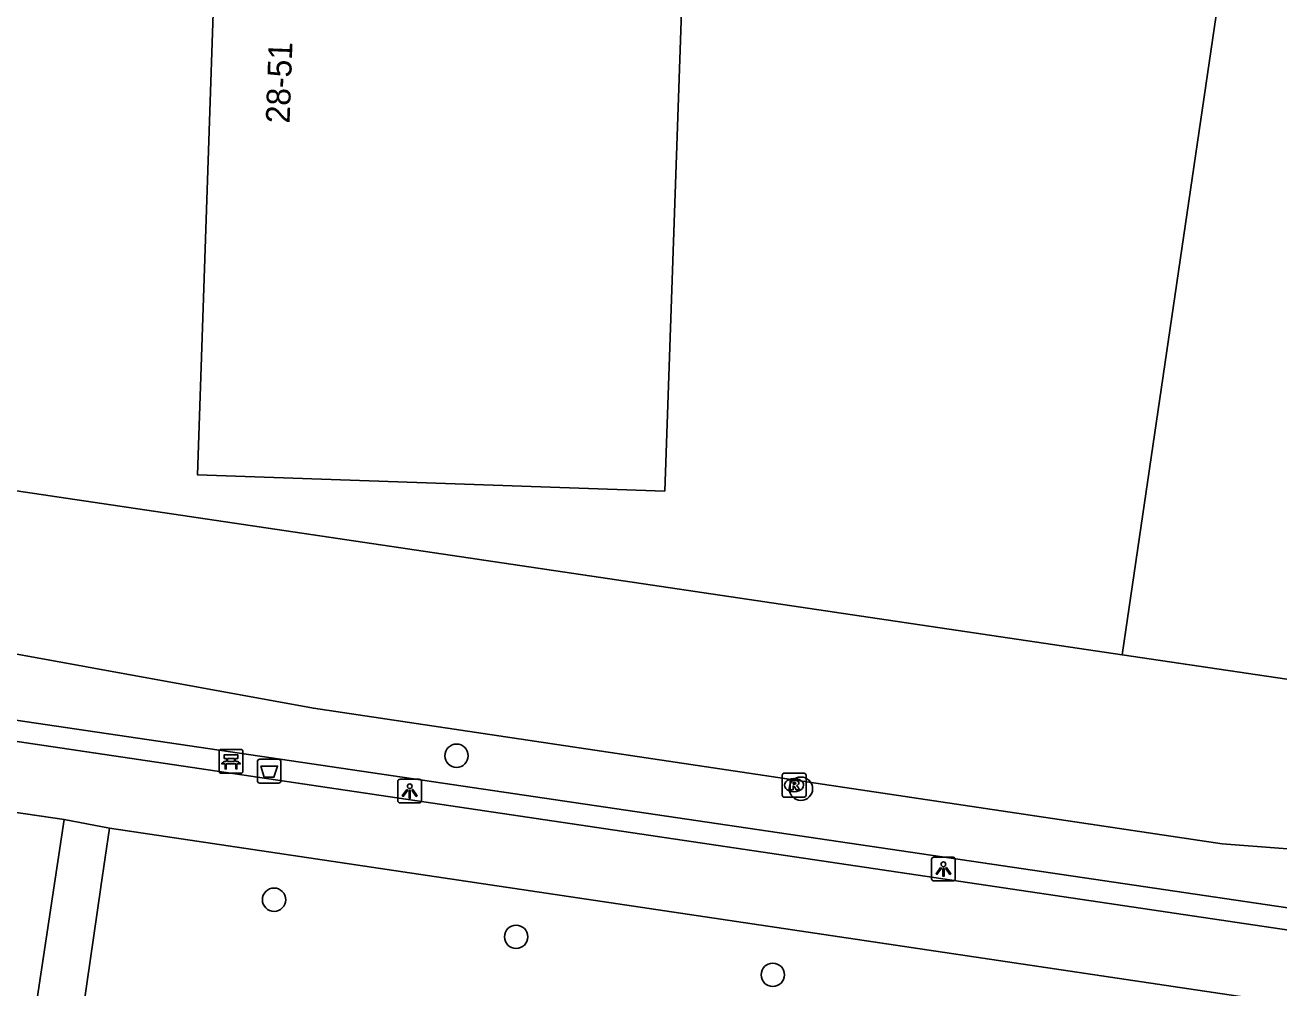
# Model space of a CAD drawing. Extents: x 164150 to 165261, y 382513 to 383432.
# Drawn here: x 164287.5 to 164340.1, y 383053.9 to 383094.3 of the extents above; entities that cross this region are included whole.
import ezdxf

# ---------------------------------------------------------------- set-up
doc = ezdxf.new("R2010")
doc.units = 0
for name, color, linetype in [('IMGEO_Afvalbak', 7, 'Continuous'), ('IMGEO_Bank', 7, 'Continuous'), ('IMGEO_Boom', 7, 'Continuous'), ('IMGEO_Fietspad_gesloten', 7, 'Continuous'), ('IMGEO_Fietspad_open', 7, 'Continuous'), ('IMGEO_Groenvoorziening', 7, 'Continuous'), ('IMGEO_Lichtpunt', 7, 'Continuous'), ('IMGEO_Muur', 7, 'Continuous'), ('IMGEO_Pand', 7, 'Continuous'), ('IMGEO_Pand_nummerreeks', 7, 'Continuous'), ('IMGEO_Rioolput', 7, 'Continuous'), ('IMGEO_Voetpad_open', 7, 'Continuous')]:
    doc.layers.add(name, color=color, linetype=linetype)

msp = doc.modelspace()

# ---------------------------------------------------------------- linework, layer by layer
at = {"layer": 'IMGEO_Afvalbak'}
for p, q in [((164297.213, 383062.583), (164297.213, 383063.383)), ((164297.213, 383063.383), (164297.213, 383062.583)), ((164297.313, 383063.483), (164298.103, 383063.483)), ((164298.103, 383063.483), (164297.313, 383063.483)), ((164298.203, 383063.383), (164298.203, 383062.583)), ((164298.203, 383062.583), (164298.203, 383063.383)), ((164298.103, 383062.483), (164297.313, 383062.483)), ((164297.313, 383062.483), (164298.103, 383062.483))]:
    msp.add_line(p, q, dxfattribs=at)
msp.add_lwpolyline([(164297.356, 383063.197), (164298.06, 383063.197), (164297.911, 383062.727), (164297.505, 383062.727), (164297.356, 383063.197)], dxfattribs=at)
for centre, start, end in [((164297.313, 383063.383), 90, 180), ((164297.313, 383063.383), 90, 180), ((164298.103, 383063.383), 0, 90), ((164298.103, 383063.383), 360, 90), ((164297.313, 383062.583), 180, 270), ((164297.313, 383062.583), 180, 270), ((164298.103, 383062.583), 270, 0), ((164298.103, 383062.583), 270, 0)]:
    msp.add_arc(centre, 0.1, start, end, dxfattribs=at)
at = {"layer": 'IMGEO_Bank'}
for p, q in [((164295.608, 383062.969), (164295.608, 383063.81)), ((164295.608, 383063.81), (164295.608, 383062.969)), ((164295.683, 383063.894), (164296.524, 383063.894)), ((164296.524, 383063.894), (164295.683, 383063.894)), ((164296.608, 383063.819), (164296.608, 383062.978)), ((164296.608, 383062.978), (164296.608, 383063.819)), ((164296.305, 383063.292), (164295.912, 383063.292)), ((164295.917, 383063.4), (164295.917, 383063.506)), ((164295.961, 383063.506), (164295.961, 383063.4)), ((164296.249, 383063.512), (164295.967, 383063.512)), ((164295.967, 383063.394), (164296.249, 383063.394)), ((164296.255, 383063.4), (164296.255, 383063.506)), ((164296.299, 383063.506), (164296.299, 383063.4)), ((164296.533, 383062.894), (164295.692, 383062.894)), ((164295.692, 383062.894), (164296.533, 383062.894))]:
    msp.add_line(p, q, dxfattribs=at)
for points in [[(164295.911, 383063.512), (164295.825, 383063.512), (164295.825, 383063.673), (164296.388, 383063.673), (164296.388, 383063.512), (164296.305, 383063.512)], [(164295.855, 383063.292), (164295.713, 383063.292), (164295.825, 383063.394), (164295.911, 383063.394)], [(164295.905, 383063.285), (164295.905, 383063.078), (164295.862, 383063.078), (164295.862, 383063.285)], [(164296.305, 383063.394), (164296.388, 383063.394), (164296.5, 383063.292), (164296.361, 383063.292)], [(164296.355, 383063.285), (164296.355, 383063.078), (164296.311, 383063.078), (164296.311, 383063.285)]]:
    msp.add_lwpolyline(points, dxfattribs=at)
for centre, radius, start, end in [((164295.686, 383063.816), 0.0779, 92.4484, 184.2845), ((164295.686, 383063.816), 0.0779, 92.4484, 184.2845), ((164296.53, 383063.816), 0.0779, 2.4484, 94.2845), ((164296.53, 383063.816), 0.0779, 2.4484, 94.2845), ((164295.855, 383063.285), 0.00671, 2.8957, 87.1043), ((164295.912, 383063.285), 0.00671, 92.8957, 177.1043), ((164295.91, 383063.505), 0.00671, 2.8957, 87.1043), ((164295.91, 383063.401), 0.00671, 272.8957, 357.1043), ((164295.967, 383063.505), 0.00671, 92.8957, 177.1043), ((164295.967, 383063.401), 0.00671, 182.8957, 267.1043), ((164296.249, 383063.505), 0.00671, 2.8957, 87.1043), ((164296.249, 383063.401), 0.00671, 272.8957, 357.1043), ((164296.306, 383063.505), 0.00671, 92.8957, 177.1043), ((164296.306, 383063.401), 0.00671, 182.8957, 267.1043), ((164296.304, 383063.285), 0.00671, 2.8957, 87.1043), ((164296.361, 383063.285), 0.00671, 92.8957, 177.1043), ((164295.686, 383062.972), 0.0779, 182.4484, 274.2845), ((164295.686, 383062.972), 0.0779, 182.4484, 274.2845), ((164296.53, 383062.972), 0.0779, 272.4484, 4.2845), ((164296.53, 383062.972), 0.0779, 272.4484, 4.2845)]:
    msp.add_arc(centre, radius, start, end, dxfattribs=at)
at = {"layer": 'IMGEO_Boom'}
for centre in [(164305.574, 383063.63), (164320.031, 383062.245), (164297.914, 383057.588), (164308.075, 383056.03), (164318.847, 383054.435)]:
    msp.add_circle(centre, 0.489, dxfattribs=at)
at = {"layer": 'IMGEO_Fietspad_gesloten'}
for points in [[(164371.722, 383051.672), (164265.706, 383067.397), (164250.971, 383069.441)], [(164289.109, 383060.95), (164241.04, 383067.994), (164239.423, 383068.201), (164236.742, 383068.586)], [(164289.109, 383060.95), (164291.001, 383060.584)], [(164291.001, 383060.584), (164349.656, 383051.856)]]:
    msp.add_lwpolyline(points, dxfattribs=at)
at = {"layer": 'IMGEO_Fietspad_open'}
for points in [[(164287.476, 383050.195), (164289.109, 383060.95)], [(164289.455, 383049.901), (164290.642, 383058.11), (164290.645, 383058.127), (164291.001, 383060.584)]]:
    msp.add_lwpolyline(points, dxfattribs=at)
at = {"layer": 'IMGEO_Groenvoorziening'}
for points in [[(164257.237, 383074.022), (164271.132, 383070.796), (164299.567, 383065.623), (164337.712, 383059.936), (164353.074, 383058.756)], [(164371.573, 383052.659), (164251.222, 383070.415)]]:
    msp.add_lwpolyline(points, dxfattribs=at)
at = {"layer": 'IMGEO_Lichtpunt'}
for p, q in [((164303.11, 383062.55), (164303.11, 383061.743)), ((164303.11, 383062.55), (164303.11, 383061.743)), ((164304.012, 383062.645), (164303.204, 383062.645)), ((164304.012, 383062.645), (164303.204, 383062.645)), ((164304.106, 383061.743), (164304.106, 383062.55)), ((164304.106, 383061.743), (164304.106, 383062.55)), ((164303.204, 383061.649), (164304.012, 383061.649)), ((164303.204, 383061.649), (164304.012, 383061.649)), ((164326.414, 383059.37), (164325.606, 383059.37)), ((164326.414, 383059.37), (164325.606, 383059.37)), ((164325.512, 383059.275), (164325.512, 383058.468)), ((164325.512, 383059.275), (164325.512, 383058.468)), ((164326.508, 383058.468), (164326.508, 383059.275)), ((164326.508, 383058.468), (164326.508, 383059.275)), ((164325.606, 383058.374), (164326.414, 383058.374)), ((164325.606, 383058.374), (164326.414, 383058.374))]:
    msp.add_line(p, q, dxfattribs=at)
for points in [[(164303.484, 383062.214), (164303.523, 383062.186), (164303.335, 383061.924), (164303.297, 383061.951), (164303.484, 383062.214)], [(164303.586, 383062.166), (164303.633, 383062.166), (164303.633, 383061.844), (164303.586, 383061.844), (164303.586, 383062.166)], [(164303.696, 383062.186), (164303.734, 383062.213), (164303.921, 383061.951), (164303.882, 383061.923), (164303.696, 383062.186)], [(164325.886, 383058.939), (164325.925, 383058.911), (164325.737, 383058.649), (164325.699, 383058.676), (164325.886, 383058.939)], [(164325.988, 383058.891), (164326.035, 383058.891), (164326.035, 383058.569), (164325.988, 383058.569), (164325.988, 383058.891)], [(164326.098, 383058.911), (164326.136, 383058.938), (164326.323, 383058.676), (164326.284, 383058.648), (164326.098, 383058.911)]]:
    msp.add_lwpolyline(points, dxfattribs=at)
for centre in [(164303.609, 383062.348), (164326.011, 383059.073)]:
    msp.add_circle(centre, 0.0994, dxfattribs=at)
for centre, start, end in [((164303.204, 383062.55), 90, 180), ((164303.204, 383062.55), 90, 180), ((164304.012, 383062.55), 0, 90), ((164304.012, 383062.55), 0, 90), ((164303.204, 383061.743), 180, 270), ((164303.204, 383061.743), 180, 270), ((164304.012, 383061.743), 270, 0), ((164304.012, 383061.743), 270, 360), ((164325.606, 383059.275), 90, 180), ((164325.606, 383059.275), 90, 180), ((164326.414, 383059.275), 0, 90), ((164326.414, 383059.275), 0, 90), ((164325.606, 383058.468), 180, 270), ((164325.606, 383058.468), 180, 270), ((164326.414, 383058.468), 270, 0), ((164326.414, 383058.468), 270, 360)]:
    msp.add_arc(centre, 0.0946, start, end, dxfattribs=at)
at = {"layer": 'IMGEO_Muur'}
msp.add_lwpolyline([(164333.515, 383067.867), (164279.36, 383075.889)], dxfattribs=at)
at = {"layer": 'IMGEO_Pand'}
for points in [[(164339.895, 383111.289), (164333.515, 383067.867)], [(164314.313, 383074.739), (164315.508, 383108.981), (164295.865, 383109.651), (164294.697, 383075.423), (164314.313, 383074.739)], [(164333.515, 383067.867), (164352.923, 383064.994), (164359.03, 383106.478)]]:
    msp.add_lwpolyline(points, dxfattribs=at)
at = {"layer": 'IMGEO_Rioolput'}
for p, q in [((164319.241, 383061.968), (164319.241, 383062.82)), ((164319.316, 383062.894), (164320.168, 383062.894)), ((164319.729, 383062.674), (164319.754, 383062.674)), ((164320.242, 383062.82), (164320.242, 383061.968)), ((164319.752, 383062.114), (164319.727, 383062.114)), ((164320.168, 383061.894), (164319.316, 383061.894))]:
    msp.add_line(p, q, dxfattribs=at)
for points in [[(164319.241, 383061.968), (164319.241, 383062.82)], [(164319.316, 383062.894), (164320.168, 383062.894)], [(164319.83, 383062.592), (164319.578, 383062.594), (164319.578, 383062.194)], [(164319.756, 383062.513), (164319.702, 383062.513), (164319.702, 383062.432)], [(164320.242, 383062.82), (164320.242, 383061.968)], [(164319.578, 383062.194), (164319.702, 383062.194), (164319.702, 383062.356), (164319.713, 383062.356)], [(164319.702, 383062.432), (164319.754, 383062.432)], [(164319.76, 383062.327), (164319.831, 383062.194), (164319.971, 383062.194), (164319.906, 383062.32)], [(164320.168, 383061.894), (164319.316, 383061.894)]]:
    msp.add_lwpolyline(points, dxfattribs=at)
for centre, radius, start, end in [((164319.318, 383062.818), 0.0765, 91.552, 178.448), ((164319.318, 383062.818), 0.0765, 91.552, 178.448), ((164319.762, 383062.417), 0.0964, 77.0061, 93.1865), ((164319.776, 383062.474), 0.0378, 276.6634, 79.6772), ((164319.829, 383062.482), 0.109, 350.3612, 89.416), ((164320.166, 383062.818), 0.0765, 1.552, 88.448), ((164320.166, 383062.818), 0.0765, 1.552, 88.448), ((164319.712, 383062.303), 0.0533, 26.0293, 88.6989), ((164319.738, 383062.621), 0.19, 274.7715, 282.9687), ((164319.827, 383062.482), 0.112, 277.5842, 350.9817), ((164319.811, 383062.267), 0.108, 29.5134, 73.7905), ((164319.318, 383061.97), 0.0765, 181.552, 268.448), ((164319.318, 383061.97), 0.0765, 181.552, 268.448), ((164320.166, 383061.97), 0.0765, 271.552, 358.448), ((164320.166, 383061.97), 0.0765, 271.552, 358.448)]:
    msp.add_arc(centre, radius, start, end, dxfattribs=at)
for centre, major_axis, ratio, start_param, end_param in [((164319.728, 383062.394), (-0.387, 0.002), 0.722429, 4.712389, 7.853982), ((164319.753, 383062.394), (-0.39, 0.002), 0.717154, 1.570796, 4.712389)]:
    msp.add_ellipse(centre, major_axis=major_axis, ratio=ratio, start_param=start_param, end_param=end_param, dxfattribs=at)
at = {"layer": 'IMGEO_Voetpad_open'}
msp.add_lwpolyline([(164279.36, 383075.889), (164333.515, 383067.867)], dxfattribs=at)

# ---------------------------------------------------------------- texts
at = {"layer": 'IMGEO_Pand_nummerreeks'}
msp.add_text('28-51', height=1, rotation=87.9161, dxfattribs=at).set_placement((164298.565, 383090.155))

doc.saveas('drawing.dxf')
